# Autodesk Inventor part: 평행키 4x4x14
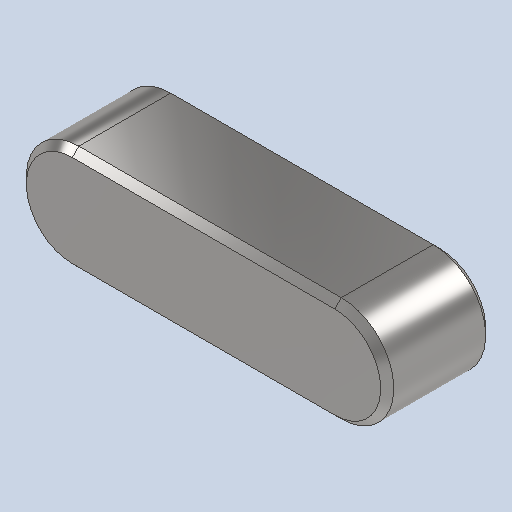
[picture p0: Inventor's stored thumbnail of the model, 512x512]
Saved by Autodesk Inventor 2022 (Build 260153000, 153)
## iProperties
Created: 2024-07
Part Number: 평행키 4x4x14
Material: 강철, 연강
Description: 키 및 해당 키홈
Document SubType Name: Modeling
Designer: PC-01
Density: 7.85 g/cm^3
Appearance: 기본값
Author: jhkim
Sending System: Autodesk Inventor 2025
Preprocessor: ST-DEVELOPER v20
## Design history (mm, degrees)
feature "Solid1"
node "솔리드1"
